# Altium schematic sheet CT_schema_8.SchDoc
size 278 x 170 mm
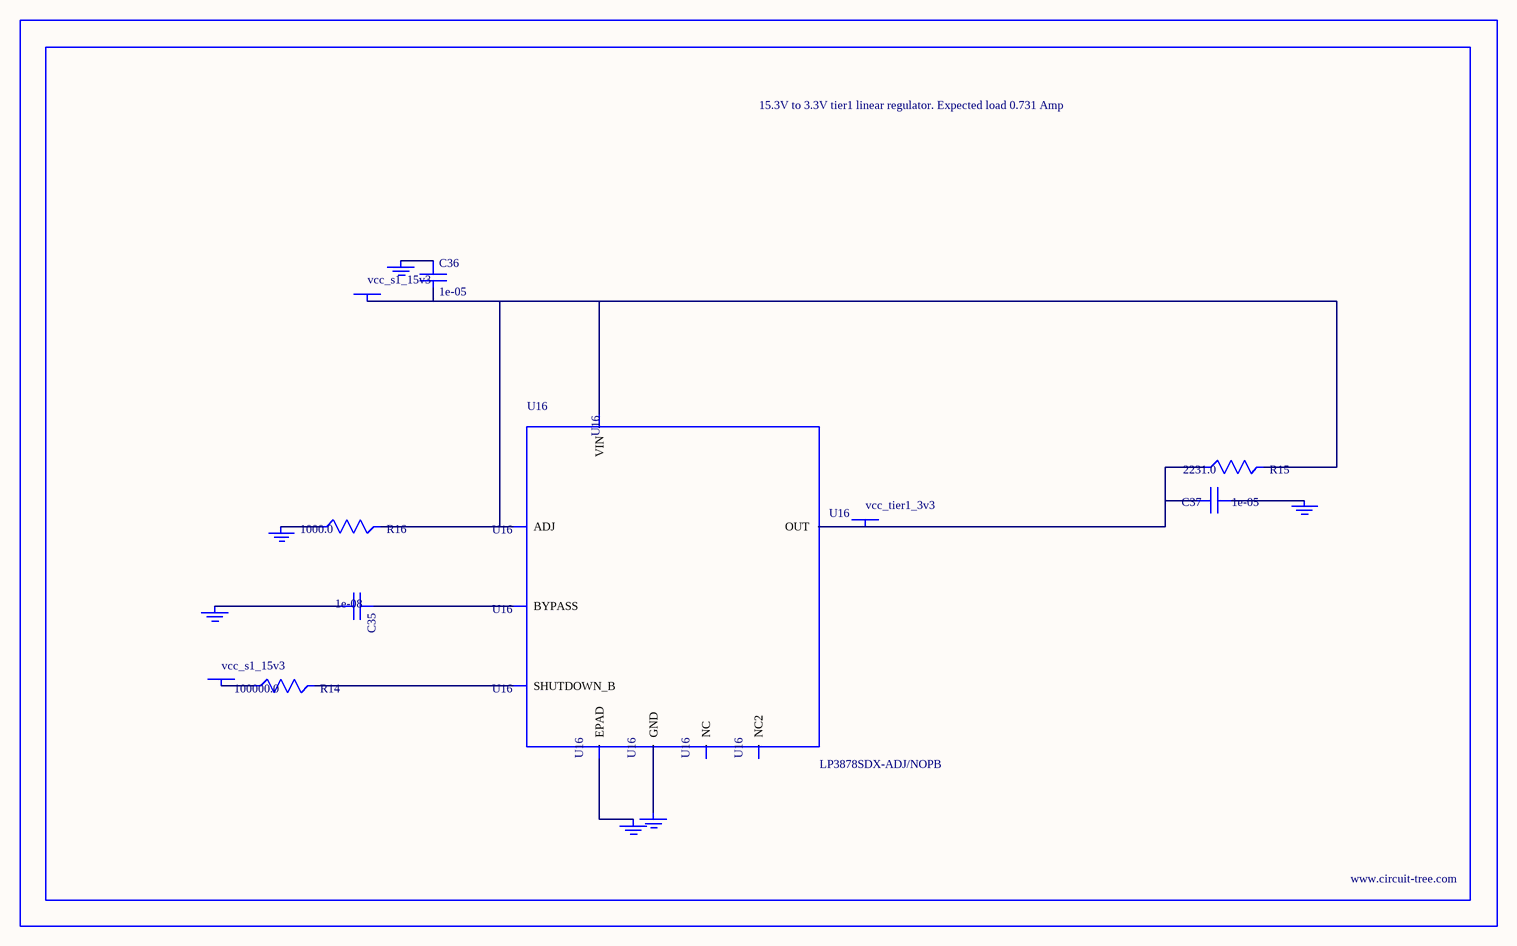
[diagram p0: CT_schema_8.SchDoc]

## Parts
BORDER7  (no value)
C35  1e-08  [C0402]
C36  1e-05  [C1210]
C37  1e-05  [C1210]
GND_INSTANCE_7_0  (no value)
GND_INSTANCE_7_1  (no value)
GND_INSTANCE_7_2  (no value)
GND_INSTANCE_7_3  (no value)
GND_INSTANCE_7_4  (no value)
GND_INSTANCE_7_5  (no value)
POWER_INSTANCE_7_0  vcc_s1_15v3
POWER_INSTANCE_7_1  vcc_s1_15v3
POWER_INSTANCE_7_2  vcc_tier1_3v3
R14  100000.0  [R0603]
R15  2231.0  [R0603]
R16  1000.0  [R0603]
U16  LP3878SDX-ADJ/NOPB  [WSON-8]

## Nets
NetC35_1: C35.1 U16.1(BYPASS)
NetC35_2: C35.2 GND_INSTANCE_7_0.0(GND)
NetC36_1: C36.1 GND_INSTANCE_7_1.0(GND)
NetC36_2: C36.2 POWER_INSTANCE_7_0.0(PWR) R15.2 R16.2 U16.4(VIN) U16.6(ADJ)
NetC37_1: C37.1 GND_INSTANCE_7_2.0(GND)
NetC37_2: C37.2 POWER_INSTANCE_7_2.0(PWR) R15.1 U16.5(OUT)
NetGND_INSTANCE_7_3_0: GND_INSTANCE_7_3.0(GND) R16.1
NetGND_INSTANCE_7_4_0: GND_INSTANCE_7_4.0(GND) U16.PAD(EPAD)
NetGND_INSTANCE_7_5_0: GND_INSTANCE_7_5.0(GND) U16.3(GND)
NetPOWER_INSTANCE_7_1_0: POWER_INSTANCE_7_1.0(PWR) R14.1
NetR14_2: R14.2 U16.8(SHUTDOWN_B)

Not connected (* = marked no-connect by the designer): U16 2(NC) 7(NC2)

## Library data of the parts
BORDER7 = BORDER_PAGE7
C35 = C0402C103K3RAC
C36 = C1210C106K5PACTU
C37 = GRM32DR61E106MA12L
GND_INSTANCE_7_0-GND_INSTANCE_7_5 = GND
POWER_INSTANCE_7_0-POWER_INSTANCE_7_2 = PWR
R14 = RC0603JR-07100KL
R15 = R15
R16 = RC0603JR-071KL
